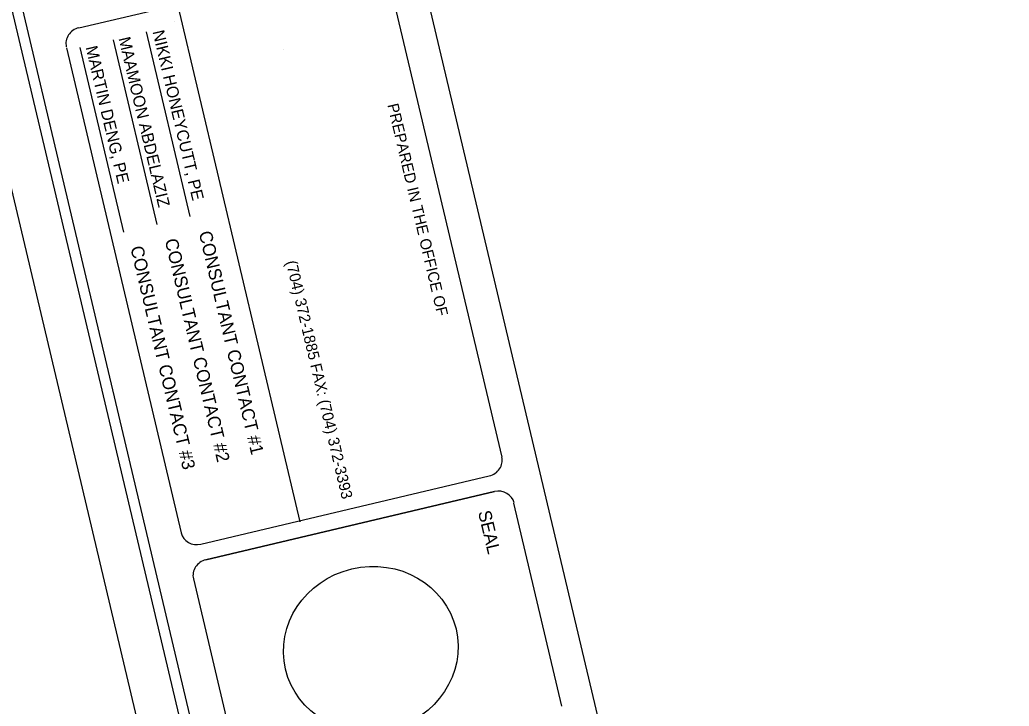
# Model space of a CAD drawing. Extents: x 1439200 to 3815465, y 598050 to 1224643.
# Drawn here: x 1440332 to 1442416, y 599535 to 600981 of the extents above; entities that cross this region are included whole.
import ezdxf

# ---------------------------------------------------------------- set-up
doc = ezdxf.new("R2010")
doc.units = 0
doc.layers.add('Exist Right of Way Line', color=7, linetype='Continuous')
doc.layers.add('Old_Level_5', color=7, linetype='Continuous')

msp = doc.modelspace()

# ---------------------------------------------------------------- linework, layer by layer
at = {"layer": 'Exist Right of Way Line'}
msp.add_lwpolyline([(1439298.8, 605293.4), (1440988.4, 598155.9), (1445527, 599230.3), (1443837.3, 606367.8)], close=True, dxfattribs=at)
at = {"layer": 'Old_Level_5'}
for p, q in [((1440363.8, 604519.2), (1441803.1, 598439.2)), ((1440456, 600964.1), (1441063.7, 601107.2)), ((1441105, 601083.4), (1441347.1, 600059.3)), ((1440664.9, 601010.8), (1440921.4, 599923.4)), ((1440658, 600977.6), (1440658, 600977.6)), ((1440528.1, 600939.2), (1440620.2, 600550)), ((1440598.2, 600955.8), (1440690.3, 600566.6)), ((1440430, 600922.1), (1440671.6, 599900.3)), ((1440457.9, 600922.6), (1440550.1, 600533.4)), ((1440888.2, 600919.1), (1440888.2, 600919.1)), ((1440713, 599876.3), (1441321, 600020.2)), ((1441332, 599987.1), (1440724, 599843.3)), ((1440724, 599843.3), (1441332, 599987.1)), ((1441332, 599987.1), (1440724, 599843.3)), ((1441372.2, 599962.8), (1441473.3, 599534.8)), ((1440697.6, 599803.4), (1440798.6, 599373.6))]:
    msp.add_line(p, q, dxfattribs=at)
msp.add_lwpolyline([(1445632.9, 599164.9), (1443909.8, 606443.8), (1439200, 605328.8), (1440923.1, 598050)], close=True, dxfattribs=at)
msp.add_lwpolyline([(1439494.5, 604562.1), (1440994.6, 598225.2)], dxfattribs=at)
for centre, major_axis, ratio, start_param, end_param in [((1440463.5, 600932.3), (33.8, 8), 0.941469, 1.570198, 3.141359), ((1441313.5, 600051.5), (33.8, 8), 0.930867, 4.711814, 6.283034), ((1441339.3, 599955.1), (33.8, 8), 0.941469, 6.283006, 7.85338), ((1440705.7, 599908), (-33.8, -8), 0.941469, 6.282951, 7.853377), ((1440731.2, 599811.3), (-33.8, -8), 0.941469, 4.711788, 6.282949)]:
    msp.add_ellipse(centre, major_axis=major_axis, ratio=ratio, start_param=start_param, end_param=end_param, dxfattribs=at)
msp.add_ellipse((1441071.2, 599655), major_axis=(-179.6, -42.5), ratio=0.941469, dxfattribs=at)

# ---------------------------------------------------------------- texts
for s, height, p in [('NIKKI HONEYCUTT, PE', 25, (1440611.1, 600956.2)), ('MAAMOON ABDELAZIZ', 25, (1440539.5, 600942)), ('MARTIN DENG, PE', 25, (1440470.1, 600923.2)), ('PREPARED IN THE OFFICE OF', 23.423, (1441106, 600801.9)), ('CONSULTANT CONTACT #2', 27.199, (1440637, 600516.8)), ('CONSULTANT CONTACT #1', 27.199, (1440708.7, 600532.7)), ('CONSULTANT CONTACT #3', 27.199, (1440564.5, 600501.2)), ('(704) 372-1885 FAX: (704) 372-3393', 23.423, (1440892.1, 600471)), ('SEAL ', 27.2, (1441297.1, 599943.8))]:
    msp.add_text(s, height=height, rotation=283.3038, dxfattribs=at).set_placement(p)

doc.saveas('drawing.dxf')
